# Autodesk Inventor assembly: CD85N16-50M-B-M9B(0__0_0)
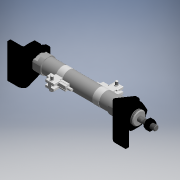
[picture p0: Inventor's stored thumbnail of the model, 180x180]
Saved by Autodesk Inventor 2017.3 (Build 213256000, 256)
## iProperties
Category: PARTsolutions
Company: SMC
Part Number: CD85N16-50M-B-M9B(0__0_0)
Catalog Web Link: www.cadenas.de
Description: C85/CD85-ISO Standard Air Cylinder:Standard Type Double Acting Single Rod
Vendor: SMC
Document SubType Name: Assembly
Designer: partserver
Manufacturer: SMC
Mass: 43.2798 g
Surface Area: 304.456 cm^2
Volume: 43.2798 cm^3
Density: 1 g/cm^3
Title: CD85N16-50M-B-M9B
Author: Cadenas PARTsolutions
Comments: ISO Standard Air Cylinder:Standard Type Double Acting Single Rod
PSOL_IDENT_0: {$CADENAS_DATA\23d-libs\smc_jp\actuator\standard_air_cylinder\c85\c85_asmtab.prj},310 {VTYP=3D},{STY
PSOL_IDENT_1: P=ASSTAB},{NB=CD85N16-50M-B-M9B(0__0_0)},{LINA=CD85N16-50M-B-M9B},{NN=C85/CD85},{DATE=09.12.2020 02:
PSOL_IDENT_2: 57:10},{GEOMDATE=01.09.2020 06:51:33},{VERSION=},{LINEID=90},{WBVAR=MAGNET,AUTOSW,LEAD,NUMBER,STROKE
PSOL_IDENT_3: ,POS,CUSHION,BOOT,BRACKET,POSITION,ACCESSORY,SWITCHMT,STOP,OMSC,THREAD},{WBNUMERIC=STROKE,POS}  {NB=
PSOL_IDENT_4: CD85N16-50M-B-M9B(0__0_0)},{LINA=CD85N16-50M-B-M9B},{KT=DUMMY},{ORDER=CD85N16-50M-B-M9B},{BORE=16},{
PSOL_IDENT_5: MOUNT=(N) Basic (Integral clevis)},{MOUNTX=N},{MAGNET=D},{AUTOSW=-M9B},{AUTOSWX='','(-) Without auto
PSOL_IDENT_6: switch','-M9N','M9N','-M9P','M9P','-M9B','M9B','-M9NV','M9NV','-M9PV','M9PV','-M9BV','M9BV','-M9NW'
PSOL_IDENT_7: ,'M9NW','-M9PW','M9PW','-M9BW','M9BW','-M9NWV','M9NWV','-M9PWV','M9PWV','-M9BWV','M9BWV','-M9NA','M9
PSOL_IDENT_8: NA','-M9PA','M9PA','-M9BA','M9BA','-M9NAV','M9NAV','-M9PAV','M9PAV','-M9BAV','M9BAV','-A90','A90','-
PSOL_IDENT_9: A93','A93','-A96','A96','-A90V','A90V','-A93V','A93V','-A96V','A96V','-H7C','H7C','-H7NF','H7NF','-C
PSOL_IDENT_10: 73C','C73C','-C80C','C80C','-J79C','J79C','-F79F','F79F','-A72','A72','-A72H','A72H','-A73C','A73C','
PSOL_IDENT_11: -A80C','A80C','-A79W','A79W'},{LEAD=},{LEADX='','(-) 0.5 m','M','(M) 1 m','L','(L) 3 m','Z','(Z) 5 m'
PSOL_IDENT_12: },{NUMBER=},{NUMBERX='','(-) 2 pcs','S','(S) 1 pc'},{STROKE=50},{STROKEX=[25:40./15.],50,80,100,125,
PSOL_IDENT_13: 160,200},{POS=0},{CUSHION=},{CUSHIONX= '', '(-) Rubber bumper (Standard)', 'C', '(C) Air cushion' },
PSOL_IDENT_14: {BOOT=},{BOOTX= '','N/A' },{BRACKET=M},{BRACKETX='','(-) None','L','(L) Single foot','M','(M) Double
PSOL_IDENT_15: foot','G','(G) Flange','U','(U) Trunnion','N','(N) Clevis'},{POSITION=},{POSITIONX='','N/A'},{ACCES
PSOL_IDENT_16: SORY=},{SWITCHMT=-B},{SWITCHMTX= '-A','(A) Rail mounting','-B','(B) Band mounting' },{STOP=0},{COM=-
PSOL_IDENT_17: },{OMSC=},{OMSCX='','(-) Without order','-XB6','(-XB6) Heat resistant cylinder (–10 to 150°C)','-XC6
PSOL_IDENT_18: A','(-XC6A) Stainless steel used on all standard iron parts','-XC6B','(-XC6B) Stainless steel rod en
PSOL_IDENT_19: d moving parts'},{THREAD=0},{MAX=400},{MAX1=200},{AU=M9A9},{SMIN=15},{SMINN=25},{TIF=NL},{PPATH=c85/
PSOL_IDENT_20: assembly/c85_asmsbl.prj}
NB: CD85N16-50M-B-M9B(0__0_0)
NN: C85/CD85
NT: ISO Standard Air Cylinder:Standard Type Double Acting Single Rod
NBSYN: $ORDER.($POS._$POSITION._$STOP._$THREAD.)
LINA: CD85N16-50M-B-M9B
CATALOG: SMC (JP
BORE: 16
MOUNT: (N) Basic (Integral clevis)
MAGNET: (D) With magnet
AUTOSW: M9B Solid state-General-Grommet-Indicator light:Yes-2 wire-In line
LEAD: (-) 0.5 m
NUMBER: (-) 2 pcs
STROKE: 50
POS: 0
CUSHION: (-) Rubber bumper (Standard)
BOOT: N/A
BRACKET: (M) Double foot
POSITION: N/A
ACCESSORY: (-) None
SWITCHMT: (B) Band mounting
STOP: Standard stroke
COM: -
OMSC: (-) Without order
THREAD: on
SUPPLIER: SMC
ARTICLENO: CD85N16-50M-B-M9B(0__0_0)
BOMINFO: CD85N16-50M-B-M9B
CREATOR: CADENAS GmbH
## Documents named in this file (7)
- e:\temp\worker_18\temp\exporttempdir_7776_18_3roKB\format_0\CD85N16-50M-B-M9B(0__0_0).iam
- e:\temp\worker_18\temp\exporttempdir_7776_18_3roKB\format_0\CD85N16-50-B-M9B(0)_BODY.ipt
- e:\temp\worker_18\temp\exporttempdir_7776_18_3roKB\format_0\C8516-50_ROD.ipt
- e:\temp\worker_18\temp\exporttempdir_7776_18_3roKB\format_0\C85NT16(16_).ipt
- e:\temp\worker_18\temp\exporttempdir_7776_18_3roKB\format_0\C85SN16(16_).ipt
- e:\temp\worker_18\temp\exporttempdir_7776_18_3roKB\format_0\D-M9B_C85_(16).ipt
- e:\temp\worker_18\temp\exporttempdir_7776_18_3roKB\format_0\C85L16_16.ipt
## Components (9 placed, 6 different names)
1. CD85N16-50-B-M9B(0)_BODY:1
2. C8516-50_ROD:1
3. C85NT16(16_):1
4. C85SN16(16_):1
5. D-M9B_C85_(16):1
6. D-M9B_C85_(16):2
7. C85L16_16:1
8. C85L16_16:2
9. C85SN16(16_):2
